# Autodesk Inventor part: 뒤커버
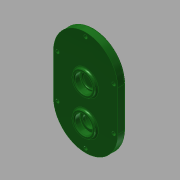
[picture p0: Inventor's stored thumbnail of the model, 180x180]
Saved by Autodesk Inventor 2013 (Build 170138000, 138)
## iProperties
Created: 2016-12
Part Number: 뒤커버
Material: 일반
Document SubType Name: Modeling
Designer: mduedu
Density: 1 g/cm^3
Mass: 87.2419 g
Surface Area: 240.701 cm^2
Volume: 87.2419 cm^3
Author: mduedu
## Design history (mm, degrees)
sketch "스케치1"
  geometry: L1 (40, -25)-(40, 25); L2 (-40, 25)-(-40, -25); L3 (-40, -25)-(40, 25); L4 (40, -25)-(-40, 25); A1 r 40 centre (0, 25) between (40, 25) and (-40, 25); A2 r 40 centre (0, -25) between (-40, -25) and (40, -25); 1 further point
  constraints: 8 end point, 4 point on circle, 4 tangent, 2 centre point, 2 midpoint, 1 parallel, 1 vertical
  dimensions: "d0" = 130 dimension on A2 A1; "d2" = 80 distance between parallel lines of L1 L2
extrude "돌출1" new body sketch "스케치1" distance "d3" = 10; taper "d4" = 0 deg
sketch "스케치2"
  geometry: C1 r 14 at (0, 11); 1 further point
  constraints: 1 centre point, 1 vertical alignment
  dimensions: "d5" = 28 diameter of C1; "d6" = 11 distance of C1.centre point (0, 0)
extrude "돌출2" join sketch "스케치2" distance "d7" = 3; taper "d8" = 0 deg
sketch "스케치3"
  geometry: C1 r 14 at (0, -33.1); C2 r 14 at (0, 11) reference; 1 further point
  constraints: 1 centre point, 1 vertical alignment
  dimensions: "d9" = 28 diameter of C1; "d69" = 44.1 distance of C1.centre C2.centre
extrude "돌출3" join sketch "스케치3" distance "d11" = 3; taper "d12" = 0 deg
hole "구멍1" diameter "d15" = 22; stored, may be unused: countersink angle "d19" = 90 deg, drill point angle "d21" = 0 deg; dims "d13" = 10, "d14" = 10, "d16" = 6, "d17" = 4, "d18" = 2, "d20" = 7
hole "구멍2" diameter "d24" = 18; stored, may be unused: countersink angle "d28" = 90 deg, drill point angle "d30" = 0 deg; dims "d22" = 10, "d23" = 10, "d25" = 6, "d26" = 4, "d27" = 2, "d29" = 1
hole "구멍3" diameter "d33" = 22; stored, may be unused: countersink angle "d37" = 90 deg, drill point angle "d39" = 0 deg; dims "d31" = 10, "d32" = 10, "d34" = 6, "d35" = 4, "d36" = 2, "d38" = 7
sketch "스케치4"
  geometry: C1 r 14 at (0, -33.1) reference; C2 r 18 at (0, -33.1); 1 further point
  constraints: 1 centre point, 1 coincident
  dimensions: "d40" = 36 diameter of C2
extrude "돌출4" join sketch "스케치4" distance "d41" = 4; taper "d42" = 0 deg
hole "구멍4" diameter "d45" = 22; stored, may be unused: countersink angle "d49" = 90 deg, drill point angle "d51" = 0 deg; dims "d43" = 10, "d44" = 10, "d46" = 6, "d47" = 4, "d48" = 2, "d50" = 7
hole "구멍5" diameter "d54" = 15; stored, may be unused: countersink angle "d58" = 90 deg, drill point angle "d60" = 0 deg; dims "d52" = 10, "d53" = 10, "d55" = 6, "d56" = 4, "d57" = 2, "d59" = 7
fillet "모깎기1" dims "d61" = 0.3
fillet "모깎기2" dims "d62" = 2
chamfer "모따기1" distance "d63" = 1; stored, may be unused: second distance "d64" = 2, angle "d65" = 45 deg
fillet "모깎기3" dims "d66" = 2
fillet "모깎기4" dims "d67" = 2
fillet "모깎기5" dims "d68" = 2
sketch "스케치5"
  geometry: L1 (-40, 25)-(-40, -25) reference; L2 (40, -25)-(40, 25) reference; L3 (35, 25)-(35, -25); L4 (-35, -25)-(-35, 25); A1 r 40 centre (0, 25) between (40, 25) and (-40, 25) reference; A2 r 40 centre (0, -25) between (-40, -25) and (40, -25) reference; A3 r 35 centre (0, 25) between (35, 25) and (-35, 25); A4 r 35 centre (0, -25) between (-35, -25) and (35, -25); 2 further points
  constraints: 5 point on circle, 4 end point, 2 centre point, 1 vertical alignment, 3 other
  dimensions: "d70" = 5 distance between parallel lines of L2 L3
sketch "스케치6"
  geometry: 1 further point
hole "구멍6" sketch "스케치6" at (0, 60) diameter "d71" = 4.5; stored, may be unused: countersink angle "d75" = 90 deg, drill point angle "d77" = 0 deg; dims "d72" = 6, "d73" = 8, "d74" = 4.6, "d76" = 8
node "솔리드1"
pattern_linear "직사각형 패턴1"
